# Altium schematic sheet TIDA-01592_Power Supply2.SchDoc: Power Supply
size 431 x 279 mm; Date: Not shown in title block; ApprovedBy: Not shown in title block; CheckedBy: Not shown in title block; Author: Not shown in title block; CompanyName: Not shown in title block; DrawnBy: Abhishek Vishwa; Engineer: Abhishek Vishwa; Organization: Not shown in title block; Address1: Not shown in title block; Address2: Not shown in title block; Address3: Not shown in title block; Address4: Not shown in title block; DocumentNumber: 1; Revision: Use project parameter SCH_Rev; SheetNumber: 3; SheetTotal: 5; PageSetup: Record=PageOptions¦CenterHorizontal=True¦CenterVertical=True¦PrintScale=1.00¦XCorrection=1.00¦YCorrection=1.00¦PrintKind=0¦BorderSize=5000000¦LeftOffset=0¦BottomOffset=0¦Orientation=2¦PaperLength=1000¦PaperWidth=1000¦Scale=100¦PaperSource=15¦PrintQuality=600¦MediaType=1¦DitherType=10¦PaperKind=Letter¦PrintScaleMode=1
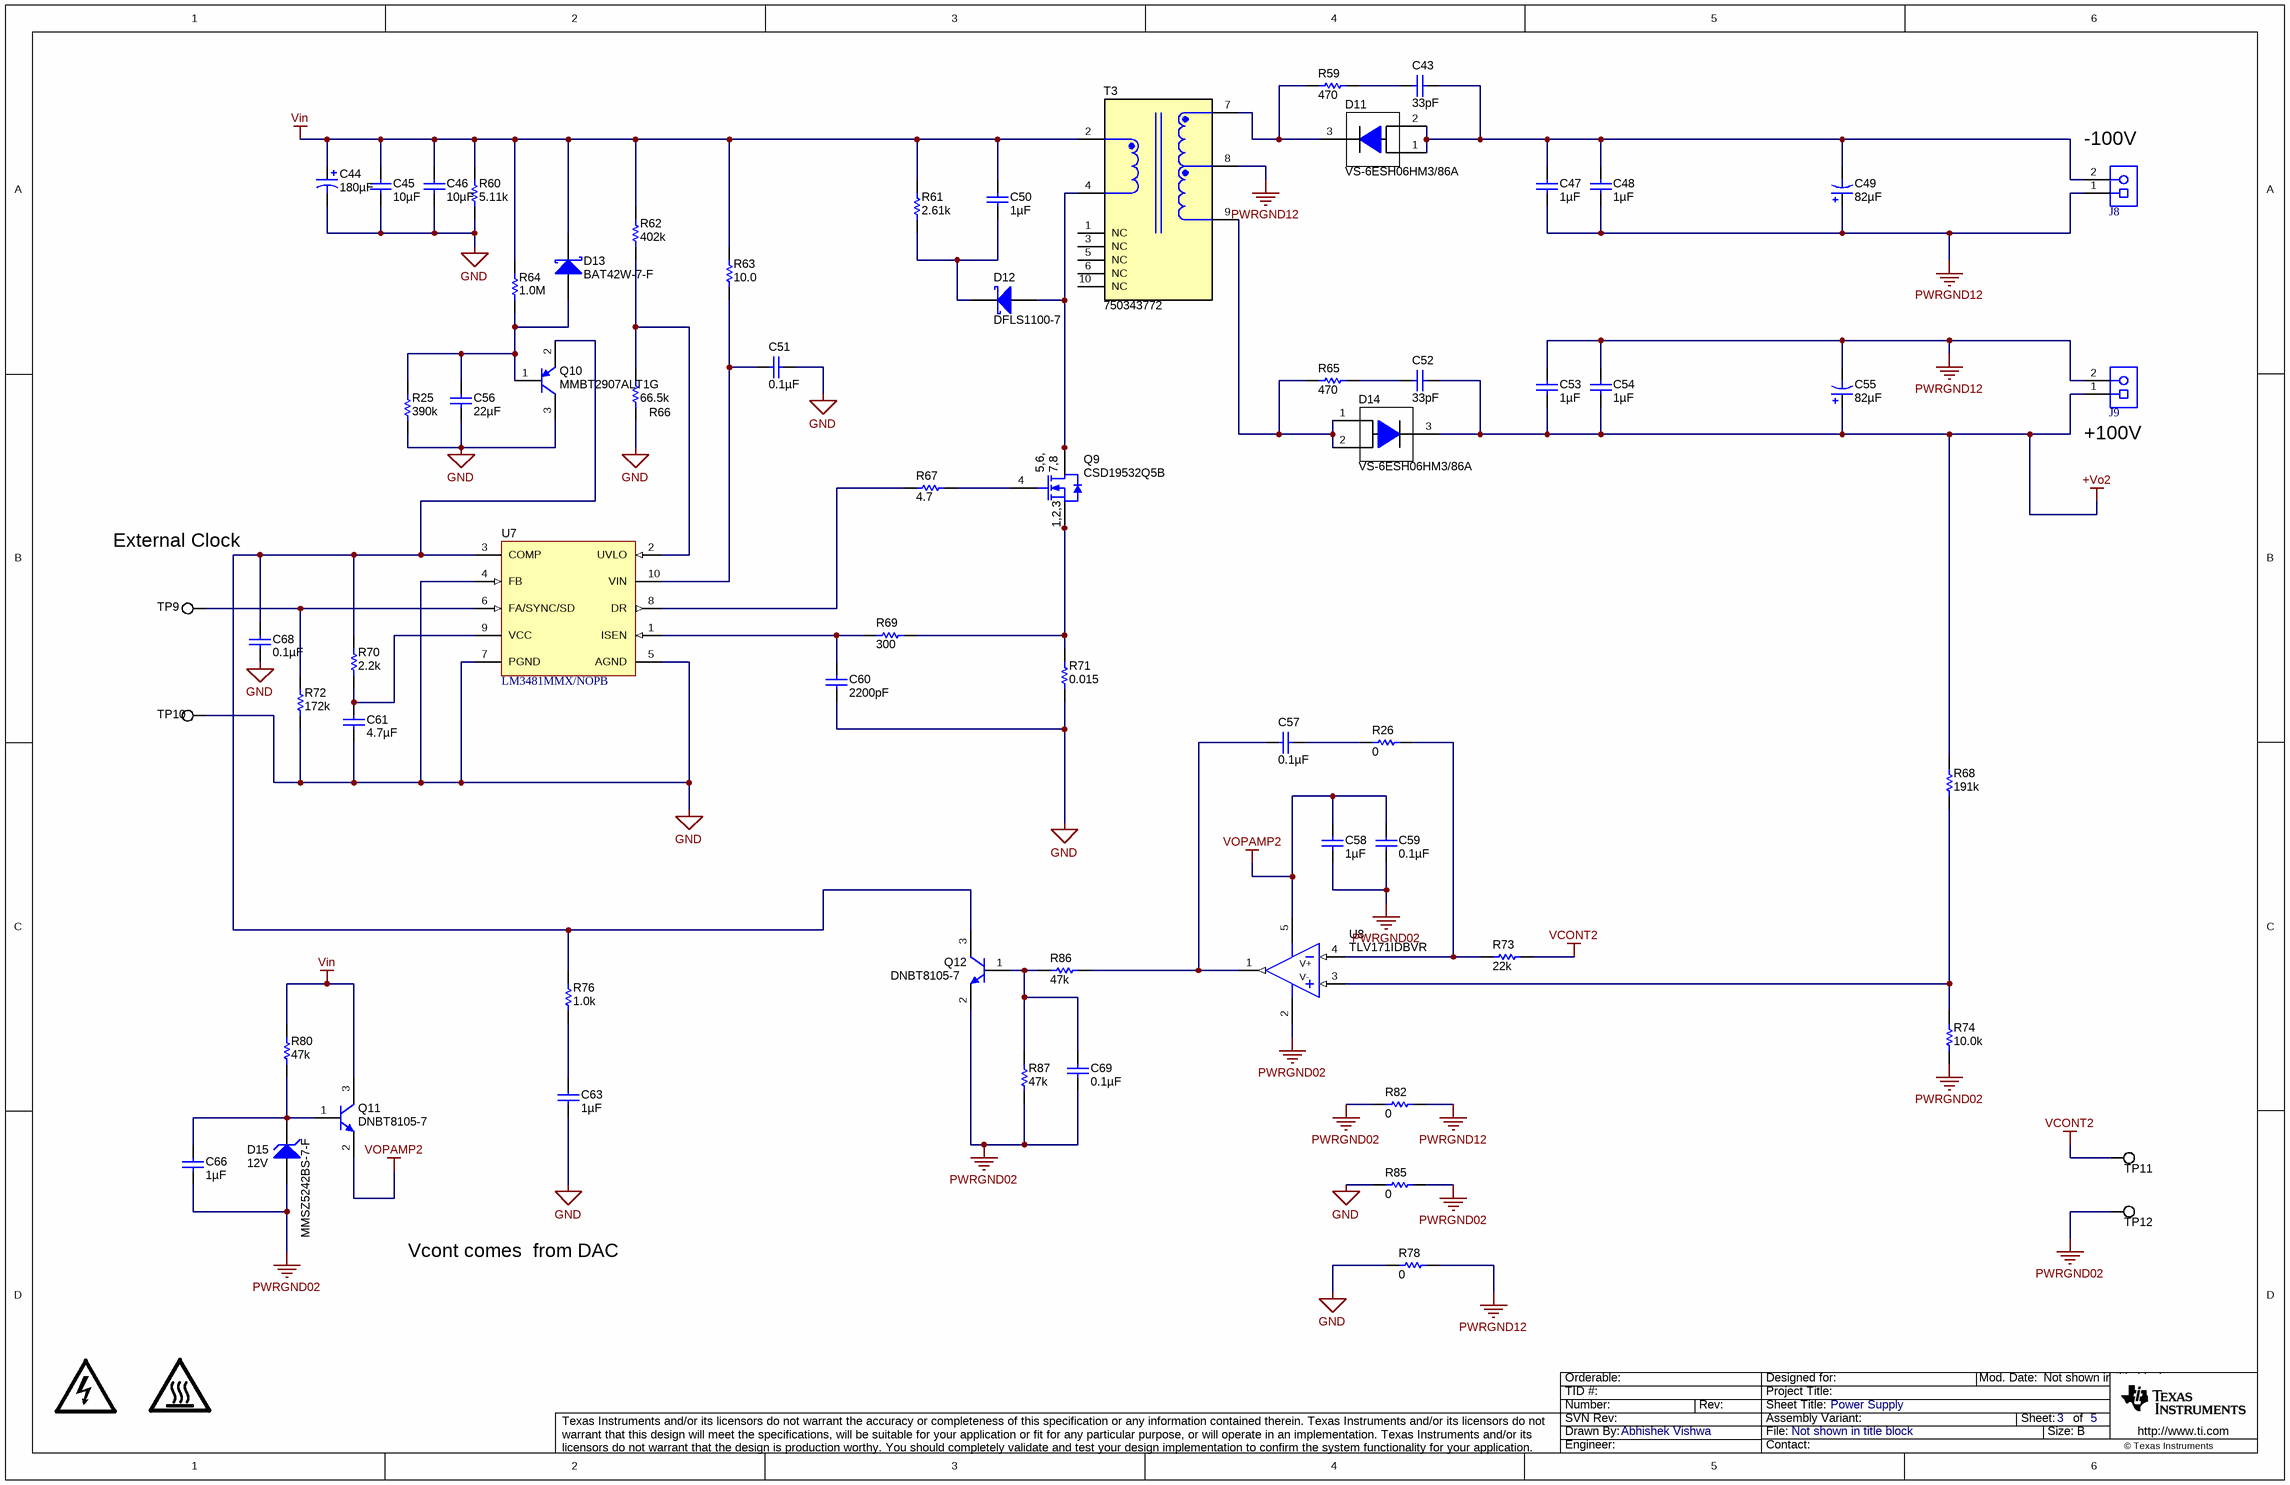
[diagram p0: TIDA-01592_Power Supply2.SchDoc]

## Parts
C43  ValueDisplayed: 33pF  [1206]  (hidden comment: 12067A330JAT2A)
C44  ValueDisplayed: 180µF  [FC_630x1120]  (hidden comment: 35TXW180MEFC6.3X25)
C45  ValueDisplayed: 10µF  [1206_180]  (hidden comment: GRM31CR61H106KA12L)
C46  ValueDisplayed: 10µF  [1206_180]  (hidden comment: GRM31CR61H106KA12L)
C47  ValueDisplayed: 1µF  [1812_180]  (hidden comment: C4532X7T2E105M250KE)
C48  ValueDisplayed: 1µF  [1812_180]  (hidden comment: C4532X7T2E105M250KE)
C49  ValueDisplayed: 82µF  [NHG_1000x2000]  (hidden comment: UCY2C820MPD9)
C50  ValueDisplayed: 1µF  [1206_180]  (hidden comment: GRM31CR72A105KA01L)
C51  ValueDisplayed: 0.1µF  [0603]  (hidden comment: GRM188R71H104KA93D)
C52  ValueDisplayed: 33pF  [1206]  (hidden comment: 12067A330JAT2A)
C53  ValueDisplayed: 1µF  [1812_180]  (hidden comment: C4532X7T2E105M250KE)
C54  ValueDisplayed: 1µF  [1812_180]  (hidden comment: C4532X7T2E105M250KE)
C55  ValueDisplayed: 82µF  [NHG_1000x2000]  (hidden comment: UCY2C820MPD9)
C56  ValueDisplayed: 22µF  [0805_HV1]  (hidden comment: C2012X5R1V226M125AC)
C57  ValueDisplayed: 0.1µF  [0603]  (hidden comment: GRM188R71H104KA93D)
C58  ValueDisplayed: 1µF  [0603]  (hidden comment: UMK107AB7105KA-T)
C59  ValueDisplayed: 0.1µF  [0603]  (hidden comment: GRM188R71H104KA93D)
C60  ValueDisplayed: 2200pF  [0402]  (hidden comment: GRM155R61H222KA01D)
C61  ValueDisplayed: 4.7µF  [0603]  (hidden comment: 0603ZD475KAT2A)
C63  ValueDisplayed: 1µF  [0603]  (hidden comment: C0603C105K3RACTU)
C66  ValueDisplayed: 1µF  [0603]  (hidden comment: C0603C105K3RACTU)
C68  ValueDisplayed: 0.1µF  [0603]  (hidden comment: GRM188R71H104KA93D)
C69  ValueDisplayed: 0.1µF  [0603]  (hidden comment: GRM188R71H104KA93D)
D11  VS-6ESH06HM3/86A  [TO-277A]
D12  DFLS1100-7  [PowerDI123]
D13  BAT42W-7-F  [SOD-123]
D14  VS-6ESH06HM3/86A  [TO-277A]
D15  MMSZ5242BS-7-F  value 12V  [SOD-323]
J8  1727010  [PhoenixConact_1727010]  (value not drawn)
J9  1727010  [PhoenixConact_1727010]  (value not drawn)
LOGO2  CAUTION HOT SURFACE  [IEC_HotSurface_Small]  (value not drawn)  (graphical)
LOGO8  DANGER HIGH VOLTAGE  [IEC_HighVoltage_Small]  (value not drawn)  (graphical)
Q9  CSD19532Q5B  [DNK0008A]
Q10  MMBT2907ALT1G  [SOT-23]
Q11  DNBT8105-7  [SOT-23]
Q12  DNBT8105-7  [SOT-23]
R25  ValueDisplayed: 390k  [0603]  (hidden comment: CRCW0603390KJNEA)
R26  ValueDisplayed: 0  [0402]  (hidden comment: CRCW04020000Z0ED)
R59  ValueDisplayed: 470  [1206]  (hidden comment: CRCW1206470RJNEA)
R60  ValueDisplayed: 5.11k  [TNPW0603]  (hidden comment: TNPW06035K11BEEA)
R61  ValueDisplayed: 2.61k  [2010]  (hidden comment: CRCW20102K61FKEF)
R62  ValueDisplayed: 402k  [0603]  (hidden comment: CRCW0603402KFKEA)
R63  R4: 10.0  [0603]  (hidden comment: CRCW060310R0FKEAHP)
R64  ValueDisplayed: 1.0M  [0603]  (hidden comment: CRCW06031M00JNEA)
R65  ValueDisplayed: 470  [1206]  (hidden comment: CRCW1206470RJNEA)
R66  ValueDisplayed: 66.5k  [0603]  (hidden comment: CRCW060366K5FKEA)
R67  ValueDisplayed: 4.7  [0603]  (hidden comment: CRCW06034R70JNEA)
R68  ValueDisplayed: 191k  [0603]  (hidden comment: CRCW0603191KFKEA)
R69  ValueDisplayed: 300  [0603]  (hidden comment: CRCW0603300RJNEA)
R70  ValueDisplayed: 2.2k  [0603]  (hidden comment: ERJ-3GEYJ222V)
R71  ValueDisplayed: 0.015  [2010]  (hidden comment: WSL2010R0150FEA18)
R72  ValueDisplayed: 172k  [0603]  (hidden comment: RT0603DRE07172KL)
R73  ValueDisplayed: 22k  [0603]  (hidden comment: CRCW060322K0JNEA)
R74  ValueDisplayed: 10.0k  [0603]  (hidden comment: CRCW060310K0FKEA)
R76  ValueDisplayed: 1.0k  [0603]  (hidden comment: CRCW06031K00JNEA)
R78  ValueDisplayed: 0  [2010L]  (hidden comment: CRCW20100000Z0EF)
R80  ValueDisplayed: 47k  [1206]  (hidden comment: CRCW120647K0JNEA)
R82  ValueDisplayed: 0  [2010L]  (hidden comment: CRCW20100000Z0EF)
R85  ValueDisplayed: 0  [2010L]  (hidden comment: CRCW20100000Z0EF)
R86  ValueDisplayed: 47k  [0603]  (hidden comment: RC0603JR-0747KL)
R87  ValueDisplayed: 47k  [0603]  (hidden comment: RC0603JR-0747KL)
T3  750343772  [Wurth_EE16_7_5_5278]
TP9  5002  [Keystone5002]  (value not drawn)
TP10  5002  [Keystone5002]  (value not drawn)
TP11  5002  [Keystone5002]  (value not drawn)
TP12  5002  [Keystone5002]  (value not drawn)
U7  LM3481MMX/NOPB  [MUB10A_N]
U8  TLV171IDBVR  [DBV0005A_N]

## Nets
+Vo2: C52.1 C53.2 C54.2 C55.1(+) D14.3(K) J9.1 R68.2
GND: C44.2(-) C45.2 C46.2 C51.1 C56.2 C60.2 C61.2 C63.2 C68.1 Q10.3(C) R25.1 R60.1 R66.1 R71.1 R72.1 R78.1 R85.1 TP10.1 U7.4(FB) U7.5(AGND) U7.7(PGND)
PWRGND02: C58.2 C59.2 C66.2 C69.1 D15.2(A) Q12.2(E) R74.2 R82.1 R85.2 R87.2 TP12.1 U8.2(V-)
PWRGND12: C47.2 C48.2 C49.1(+) C53.1 C54.1 C55.2(-) J8.1 J9.2 R78.2 R82.2 T3.8
VCONT2: R73.2 TP11.1
Vin: C44.1(+) C45.1 C46.1 C50.1 D13.1(K) Q11.3(C) R60.2 R61.2 R62.2 R63.1 R64.2 R80.2 T3.2
VOPAMP2: C58.1 C59.1 Q11.2(E) U8.5(V+)
NetC43_1: C43.1 C47.1 C48.1 C49.2(-) D11.1(A) D11.2(A) J8.2
NetC43_2: C43.2 R59.2
NetC50_2: C50.2 D12.1(K) R61.1
NetC51_2: C51.2 R63.2 U7.10(VIN)
NetC52_2: C52.2 R65.2
NetC56_1: C56.1 D13.2(A) Q10.1(B) R25.2 R64.1
NetC57_1: C57.1 R86.1 U8.1(OUT)
NetC57_2: C57.2 R26.1
NetC60_1: C60.1 R69.1 U7.1(ISEN)
NetC61_1: C61.1 R70.2 U7.9(VCC)
NetC63_1: C63.1 R76.1
NetC66_1: C66.1 D15.1(K) Q11.1(B) R80.1
NetC68_2: C68.2 Q10.2(E) Q12.3(C) R70.1 R76.2 U7.3(COMP)
NetC69_2: C69.2 Q12.1(B) R86.2 R87.1
NetD11_3: D11.3(K) R59.1 T3.7
NetD12_2: D12.2(A) Q9.5(D) Q9.6(D) Q9.7(D) Q9.8(D) Q9.9(D) T3.4
NetD14_1: D14.1(A) D14.2(A) R65.1 T3.9
NetQ9_1: Q9.1(S) Q9.2(S) Q9.3(S) R69.2 R71.2
NetQ9_4: Q9.4(G) R67.2
NetR26_2: R26.2 R73.1 U8.4(IN-)
NetR62_1: R62.1 R66.2 U7.2(UVLO)
NetR67_1: R67.1 U7.8(DR)
NetR68_1: R68.1 R74.1 U8.3(IN+)
NetR72_2: R72.2 TP9.1 U7.6(FA/SYNC/SD)

Not connected (* = marked no-connect by the designer): T3 1(NC) 3(NC) 5(NC) 6(NC) 10(NC)

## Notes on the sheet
- (near J8) -100V
- (near J9) +100V
- External Clock Synchronization
- Vcont comes  from DAC

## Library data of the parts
C43 C52 = 12067A330JAT2A: CAP, CERM, 33 pF, 500 V,+/- 5%, C0G/NP0, 1206; Manufacturer: AVX; Polarized: N; CompType: Capacitor; Value: 33pF; U/M: EA; Cap_F: 0.000000000033; Tolerance_%: 5; VDC_V: 500; Value2: 500V; TaMin_C: -55; TaMax_C: 125; SizeArea_mm2: 5.12; SizeAreaWB_mm2: 10.92; SizeX_mm: 3.2; SizeY_mm: 1.6; SizeZ_mm: 1.35; AEC Category: Q200; Green_Lifecycle: Not Set; Green_REACh: Incomplete
C44 = EEU-FC1V470: CAP, AL, 180 µF, 35 V, +/- 20%, TH; Manufacturer: Rubycon; Polarized: Y; CompType: Capacitor; Value: 180uF; U/M: EA; Cap_F: 0.000180; Tolerance_%: 20; VDC_V: 35; Value2: 35V; IRMS_A: 0.29; TaMin_C: -55; TaMax_C: 105; Cap_Case: 6.3x11.2mm; SizeAreaWB_mm2: 68.89; SizeArea_mm2: 39.69; SizeX_mm: 6.3; SizeZ_mm: 12.2; AEC Category: Q200; AEC Grade: 2
C45 C46 = GRM31CR61H106KA12L: CAP, CERM, 10 µF, 50 V,+/- 10%, X5R, 1206; Manufacturer: MuRata; Polarized: N; CompType: Capacitor; Value: 10uF; U/M: EA; Cap_F: 0.00001; Tolerance_%: 10; VDC_V: 50; Value2: 50V; TaMin_C: -55; TaMax_C: 85; Cap_Case: 1206; SizeArea_mm2: 5.12; SizeAreaWB_mm2: 10.92; SizeX_mm: 3.2; SizeY_mm: 1.6; SizeZ_mm: 1.8; AEC Category: Q200; Green_Lifecycle: Active; Green_REACh: Passed
C47 C48 C53 C54 = C4532X7R1H105K160KA: CAP, CERM, 1 µF, 250 V,+/- 20%, X7T, 1812; Manufacturer: TDK Corporation; Polarized: N; CompType: Capacitor; Value: 1uF; U/M: EA; Cap_F: 0.000001; Tolerance_%: 20; ESR_ohm: 0.007217; Value1: 0.007217 ohm; VDC_V: 50; Value2: 250V; IRMS_A: 2.85919; TaMin_C: -55; TaMax_C: 125; Cap_Case: 1812; SizeArea_mm2: 14.4; SizeAreaWB_mm2: 23.1; SizeX_mm: 4.5; SizeY_mm: 3.2; SizeZ_mm: 1.8; AEC Category: Q200
C49 C55 = ECA-2AHG101: CAP, AL, 82 µF, 160 V, +/- 20%, TH; Manufacturer: Nichicon; Polarized: Y; CompType: Capacitor; Value: 82uF; U/M: EA; Cap_F: 0.0001; Tolerance_%: 20; VDC_V: 160; Value2: 160V; IRMS_A: 0.265; TaMin_C: -55; TaMax_C: 105; Cap_Case: 10x20mm; SizeAreaWB_mm2: 144; SizeArea_mm2: 100; SizeX_mm: 10; SizeZ_mm: 22; AEC Category: Q200; Green_Lifecycle: Active; Green_REACh: Passed
C50 = GRM31CR72A105KA01L: CAP, CERM, 1 µF, 100 V,+/- 10%, X7R, 1206; Manufacturer: MuRata; Polarized: N; CompType: Capacitor; Value: 1uF; U/M: EA; Cap_F: 0.000001; Tolerance_%: 10; VDC_V: 100; Value2: 100V; TaMin_C: -55; TaMax_C: 125; Cap_Case: 1206; SizeArea_mm2: 5.12; SizeAreaWB_mm2: 10.92; SizeX_mm: 3.2; SizeY_mm: 1.6; SizeZ_mm: 1.8; AEC Category: Q200; Green_Lifecycle: Active; Green_REACh: Passed
C51 C57 C59 C68 C69 = GRM188R71H104KA93D: CAP, CERM, 0.1 µF, 50 V,+/- 10%, X7R, 0603; Manufacturer: MuRata; Polarized: N; CompType: Capacitor; Value: 0.1uF; U/M: EA; Cap_F: 0.0000001; Tolerance_%: 10; VDC_V: 50; Value2: 50V; TaMin_C: -55; TaMax_C: 125; SizeArea_mm2: 1.28; SizeAreaWB_mm2: 4.68; SizeX_mm: 1.6; SizeY_mm: 0.8; SizeZ_mm: 1; AEC Category: Q200; Green_Lifecycle: Active; Green_REACh: Passed
C56 = GRM21BC81C226ME44L: CAP, CERM, 22 µF, 35 V,+/- 20%, X5R, 0805; Manufacturer: TDK Corporation; Polarized: N; CompType: Capacitor; Value: 22uF; U/M: EA; Cap_F: 0.000022; Tolerance_%: 20; VDC_V: 16; Value2: 35V; TempCo: X6S; TaMin_C: -55; TaMax_C: 105; Cap_Case: 0805; SizeArea_mm2: 2.5; SizeAreaWB_mm2: 6.75; SizeX_mm: 2; SizeY_mm: 1.25; SizeZ_mm: 1.45; AEC Category: Q200
C58 = UMK107AB7105KA-T: CAP, CERM, 1 µF, 50 V,+/- 10%, X7R, 0603; Manufacturer: Taiyo Yuden; Polarized: N; CompType: Capacitor; Value: 1uF; U/M: EA; Cap_F: 0.000001; Tolerance_%: 10; VDC_V: 50; Value2: 50V; TaMin_C: -55; TaMax_C: 125; SizeArea_mm2: 1.28; SizeAreaWB_mm2: 4.68; SizeX_mm: 1.6; SizeY_mm: 0.8; SizeZ_mm: 1; AEC Category: Q200; Green_Lifecycle: Active; Green_REACh: Passed
C60 = GRM155R61H222KA01D: CAP, CERM, 2200 pF, 50 V,+/- 10%, X5R, 0402; Manufacturer: MuRata; Polarized: N; CompType: Capacitor; Value: 2200pF; U/M: EA; Cap_F: 0.0000000022; Tolerance_%: 10; VDC_V: 50; Value2: 50V; TaMin_C: -55; TaMax_C: 85; SizeArea_mm2: 0.5; SizeAreaWB_mm2: 3; SizeX_mm: 1; SizeZ_mm: 0.6; AEC Category: Q200; Green_Lifecycle: Active; Green_REACh: Passed
C61 = 0603ZD475KAT2A: CAP, CERM, 4.7 µF, 10 V,+/- 10%, X5R, 0603; Manufacturer: AVX; Polarized: N; CompType: Capacitor; Value: 4.7uF; U/M: EA; Cap_F: 0.0000047; Tolerance_%: 10; Value2: 10V; TaMin_C: -55; TaMax_C: 85; SizeArea_mm2: 1.28; SizeAreaWB_mm2: 4.68; SizeX_mm: 1.6; SizeY_mm: 0.8; SizeZ_mm: 1; AEC Category: Q200; Green_Lifecycle: Active; Green_REACh: Passed
C63 C66 = C0603C105K3RACTU: CAP, CERM, 1 µF, 25 V,+/- 10%, X7R, 0603; Manufacturer: Kemet; Polarized: N; CompType: Capacitor; Value: 1uF; U/M: EA; Cap_F: 0.000001; Tolerance_%: 10; VDC_V: 25; Value2: 25V; TaMin_C: -55; TaMax_C: 125; SizeArea_mm2: 1.28; SizeAreaWB_mm2: 4.68; SizeX_mm: 1.6; SizeY_mm: 0.8; SizeZ_mm: 1; AEC Category: Q200; Green_Lifecycle: Active; Green_REACh: Passed
D11 D14 = VS-6ESH06HM3/86A: Diode, Hyperfast, 600 V, 6 A, AEC-Q101, TO-277A; Manufacturer: Vishay-Semiconductor; SymbolCreator: a0412235; U/M: EA; Vf_V: 1.05; Value: 600V; Value1: 6A; Value2: 1.05V; Io_A: 6; Vr_V: 600; TJmax_C: 175; RJC_CperW: 3.5; SizeAreaWB_mm2: 57.375; SizeArea_mm2: 30.875; SizeX_mm: 6.5; SizeY_mm: 4.75; SizeZ_mm: 1.2; AEC Category: Q101; AEC Qualified: Y
D12 = DFLS1100-7: Diode, Schottky, 100 V, 1 A, PowerDI123; Manufacturer: Diodes Inc.; U/M: EA; Vf_V: 0.77; Value: 100V; Value1: 1A; Value2: 0.77V; Io_A: 1; Vr_V: 100; TJmax_C: 175; RJC_CperW: 7; SizeAreaWB_mm2: 13.066; SizeArea_mm2: 6.586; SizeX_mm: 3.7; SizeY_mm: 1.78; SizeZ_mm: 0.98; AEC Category: Q101; Green_Lifecycle: Active; Green_REACh: Passed
D13 = BAT42W-7-F: Diode, Schottky, 30 V, 0.2 A, SOD-123; Manufacturer: Diodes Inc.; U/M: EA; Vf_V: 1; Value: 30V; Value1: 0.2A; Value2: 1V; Io_A: 0.2; Vr_V: 30; SizeAreaWB_mm2: 13.095; SizeArea_mm2: 6.545; SizeX_mm: 3.85; SizeY_mm: 1.7; SizeZ_mm: 1.35; AEC Category: Q101; Green_Lifecycle: Not Set; Green_REACh: Incomplete
D15 = MMSZ5242BS-7-F: Diode, Zener, 12 V, 200 mW, SOD-323; Manufacturer: Diodes Inc.; SymbolCreator: a0412235; U/M: EA; Power_W: 0.2; Vz_V: 12; Value1: 0.2W; RJA_CperW: 350; SizeAreaWB_mm2: 8.695; SizeArea_mm2: 3.645; SizeX_mm: 2.7; SizeY_mm: 1.35; SizeZ_mm: 1; AEC Category: Q101
J8 J9 = 1727010: Conn Term Block, 2POS, 3.81mm, TH; Manufacturer: Phoenix Contact; SymbolCreator: a0412235; CompType: Terminal Block
LOGO2 = IEC_HotSurface: IEC 61010-1 Hot Surface Warning; SymbolCreator: a0412235
LOGO8 = IEC_HighVoltage: IEC 61010-1 High Voltage Warning; SymbolCreator: a0412235
Q9 = CSD19532Q5B: MOSFET, N-CH, 100 V, 17 A, DNK0008A (VSON-CLIP-8); Manufacturer: Texas Instruments; Alternate Manufacturer: None; U/M: EA; ChType: N; Value: 100V; VdsMax_V: 100; Value1: ? ohm; Value2: 48 nC; QgTyp_nC: 48; Vgs_V: 20; IdsMax_A: 17; SizeAreaWB_mm2: 56; SizeArea_mm2: 30; SizeX_mm: 6; SizeY_mm: 5; SizeZ_mm: 1; AEC Category: Q101
Q10 = MMBT2907ALT1G, ON Semiconductor: Transistor, PNP, 60 V, 0.6 A, SOT-23; CompType: BJT; PNP: 1; NPN: 0; Vceo_V: 60; Vcesat1_V: 1.6; Value: 60 V; IcRated_A: 0.6; Value1: 0.6 A; TaMin_C: -55; TaMax_C: 150; SizeAreaWB_mm2: 14; SizeArea_mm2: 7.5; SizeX_mm: 2.5; SizeY_mm: 3; SizeZ_mm: 1.1; U/M: EA; AEC Category: Q101; Green_Lifecycle: Active; Green_REACh: Passed
Q11 Q12 = DNBT8105-7, Diodes Inc.: Transistor, NPN, 60 V, 1 A, AEC-Q101, SOT-23; CompType: BJT; PNP: 0; NPN: 1; Vceo_V: 60; Vcesat1_V: 0.25; Value: 60 V; Value1: 1 A; HfeMax: 300; TaMin_C: -55; TaMax_C: 150; SizeAreaWB_mm2: 14; SizeArea_mm2: 7.5; SizeX_mm: 2.5; SizeY_mm: 3; SizeZ_mm: 1.1; U/M: EA; AEC Category: Q101; AEC Qualified: Y; Green_Lifecycle: Not Set; Green_REACh: Incomplete
R25 = CRCW0603390KJNEA: RES, 390 k, 5%, 0.1 W, 0603; Manufacturer: Vishay-Dale; CompType: Resistor; Value: 390k; Res_ohm: 390000; Tolerance_%: 5; Power_W: 0.1; Value2: 0.1W; VDC_V: 75; TempCo: 200 ppm/C; SizeArea_mm2: 1.28; SizeX_mm: 1.6; SizeY_mm: 0.8; SizeZ_mm: 1; EIA_Code: E24; U/M: EA; AEC Category: Q200
R26 = CRCW04020000Z0ED: RES, 0, 5%, 0.063 W, 0402; Manufacturer: Vishay-Dale; CompType: Resistor; Value: 0; Value_Code: 0000; Tolerance_%: 5; Power_W: 0.063; Value2: 0.063W; VDC_V: 50; TempCo: 200 ppm/C; SizeArea_mm2: 0.5; SizeX_mm: 1; SizeZ_mm: 0.6; EIA_Code: E24; U/M: EA; AEC Category: Q200; Green_Lifecycle: Active; Green_REACh: Passed
R59 R65 = CRCW1206470RJNEA: RES, 470, 5%, 0.25 W, 1206; Manufacturer: Vishay-Dale; CompType: Resistor; Value: 470; Value_Code: 470R; Tolerance_%: 5; Power_W: 0.25; Value2: 0.25W; VDC_V: 200; TempCo: 200 ppm/C; SizeArea_mm2: 5.12; SizeX_mm: 3.2; SizeY_mm: 1.6; SizeZ_mm: 1.35; EIA_Code: E24; U/M: EA; AEC Category: Q200
R60 = TNPW06035K11BEEA: RES, 5.11 k, 0.1%, 0.1 W, AEC-Q200 Grade 1, 0603; Manufacturer: Vishay-Dale; CompType: Resistor; Value: 5.11k; Res_ohm: 5110; Value_Code: 5k11; Tolerance_%: 0.1; Value2: 0.1W; VDC_V: 75; TempCo: 25 ppm/C; SizeArea_mm2: 1.36; SizeX_mm: 1.6; SizeY_mm: 0.85; SizeZ_mm: 0.55; EIA_Code: E192; U/M: EA; AEC Category: Q200; AEC Qualified: Y; AEC Grade: 1
R61 = CRCW20102K61FKEF: RES, 2.61 k, 1%, 0.75 W, AEC-Q200 Grade 0, 2010; Manufacturer: Vishay-Dale; CompType: Resistor; Value: 2.61k; Res_ohm: 2610; Value_Code: 2k61; Tolerance_%: 1; Power_W: 0.75; Value2: 0.75W; VDC_V: 400; TempCo: 100 ppm/C; SizeArea_mm2: 12.5; SizeX_mm: 5; SizeY_mm: 2.5; SizeZ_mm: 1.66; EIA_Code: E96; U/M: EA; AEC Category: Q200; AEC Qualified: Y; AEC Grade: 0
R62 = CRCW0603402KFKEA: RES, 402 k, 1%, 0.1 W, 0603; Manufacturer: Vishay-Dale; CompType: Resistor; Value: 402k; Res_ohm: 402000; Tolerance_%: 1; Power_W: 0.1; Value2: 0.1W; VDC_V: 75; TempCo: 100 ppm/C; SizeArea_mm2: 1.28; SizeX_mm: 1.6; SizeY_mm: 0.8; EIA_Code: E96; U/M: EA; AEC Category: Q200; Green_Lifecycle: Active; Green_REACh: Passed
R63 = CRCW060310R0FKEAHP: RES, 10.0, 1%, 0.25 W, 0603; Manufacturer: Vishay-Dale; CompType: Resistor; Value: 10.0; Res_ohm: 10; Value_Code: 10R0; Tolerance_%: 1; Power_W: 0.25; Value2: 0.25W; VDC_V: 75; TempCo: 100 ppm/C; SizeArea_mm2: 1.28; SizeX_mm: 1.6; SizeY_mm: 0.8; EIA_Code: E96; U/M: EA; AEC Category: Q200; Green_Lifecycle: Active; Green_REACh: Passed
R64 = CRCW06031M00JNEA: RES, 1.0 M, 5%, 0.1 W, 0603; Manufacturer: Vishay-Dale; CompType: Resistor; Value: 1.0Meg; Res_ohm: 1000000; Value_Code: 1M00; Tolerance_%: 5; Power_W: 0.1; Value2: 0.1W; VDC_V: 75; TempCo: 200 ppm/C; SizeArea_mm2: 1.28; SizeX_mm: 1.6; SizeY_mm: 0.8; SizeZ_mm: 1; EIA_Code: E24; U/M: EA; AEC Category: Q200; Green_Lifecycle: Active; Green_REACh: Passed
R66 = CRCW060366K5FKEA: RES, 66.5 k, 1%, 0.1 W, 0603; Manufacturer: Vishay-Dale; CompType: Resistor; Value: 66.5k; Res_ohm: 66500; Value_Code: 66k5; Tolerance_%: 1; Power_W: 0.1; Value2: 0.1W; VDC_V: 75; TempCo: 100 ppm/C; SizeArea_mm2: 1.28; SizeX_mm: 1.6; SizeY_mm: 0.8; EIA_Code: E96; U/M: EA; AEC Category: Q200; Green_Lifecycle: Active; Green_REACh: Passed
R67 = CRCW06034R70JNEA: RES, 4.7, 5%, 0.1 W, 0603; Manufacturer: Vishay-Dale; CompType: Resistor; Value: 4.7; Value_Code: 4R70; Tolerance_%: 5; Power_W: 0.1; Value2: 0.1W; VDC_V: 75; TempCo: 200 ppm/C; SizeArea_mm2: 1.28; SizeX_mm: 1.6; SizeY_mm: 0.8; SizeZ_mm: 1; EIA_Code: E24; U/M: EA; AEC Category: Q200; Green_Lifecycle: Active; Green_REACh: Passed
R68 = CRCW0603191KFKEA: RES, 191 k, 1%, 0.1 W, 0603; Manufacturer: Vishay-Dale; CompType: Resistor; Value: 191k; Res_ohm: 191000; Tolerance_%: 1; Power_W: 0.1; Value2: 0.1W; VDC_V: 75; TempCo: 100 ppm/C; SizeArea_mm2: 1.28; SizeX_mm: 1.6; SizeY_mm: 0.8; EIA_Code: E96; U/M: EA; AEC Category: Q200; Green_Lifecycle: Active; Green_REACh: Passed
R69 = CRCW0603300RJNEA: RES, 300, 5%, 0.1 W, 0603; Manufacturer: Vishay-Dale; CompType: Resistor; Value: 300; Value_Code: 300R; Tolerance_%: 5; Power_W: 0.1; Value2: 0.1W; VDC_V: 75; TempCo: 200 ppm/C; SizeArea_mm2: 1.28; SizeX_mm: 1.6; SizeY_mm: 0.8; SizeZ_mm: 1; EIA_Code: E24; U/M: EA; AEC Category: Q200; Green_Lifecycle: Active; Green_REACh: Passed
R70 = ERJ-3GEYJ222V: RES, 2.2 k, 5%, 0.1 W, AEC-Q200 Grade 0, 0603; Manufacturer: Panasonic; CompType: Resistor; Value: 2.2k; Res_ohm: 2200; Value_Code: 2k20; Tolerance_%: 5; Power_W: 0.1; Value2: 0.1W; VDC_V: 75; TempCo: 200 ppm/C; SizeArea_mm2: 1.28; SizeX_mm: 1.6; SizeY_mm: 0.8; SizeZ_mm: 1; EIA_Code: E24; U/M: EA; AEC Category: Q200; AEC Qualified: Y; AEC Grade: 0; Green_Lifecycle: Active; Green_REACh: Passed
R71 = WSL2010R0150FEA18: RES, 0.015, 1%, 1 W, 2010; Manufacturer: Vishay-Dale; CompType: Resistor; Value: 0.015; Value_Code: R015; Tolerance_%: 1; Value2: 1W; TempCo: 75 ppm/C; SizeArea_mm2: 12.5; SizeX_mm: 5; SizeY_mm: 2.5; SizeZ_mm: 1.66; EIA_Code: E96; U/M: EA; AEC Category: Q200
R72 = RT0603DRE07172KL: RES, 172 k, 0.5%, 0.1 W, 0603; Manufacturer: Yageo America; CompType: Resistor; Value: 172k; Res_ohm: 172000; Tolerance_%: 0.5; Power_W: 0.1; Value2: 0.1W; VDC_V: 75; TempCo: 50 ppm/C; SizeArea_mm2: 1.28; SizeX_mm: 1.6; SizeY_mm: 0.8; SizeZ_mm: 1; EIA_Code: E192; U/M: EA; AEC Category: Q200
R73 = CRCW060322K0JNEA: RES, 22 k, 5%, 0.1 W, 0603; Manufacturer: Vishay-Dale; CompType: Resistor; Value: 22k; Res_ohm: 22000; Value_Code: 22k0; Tolerance_%: 5; Power_W: 0.1; Value2: 0.1W; VDC_V: 75; TempCo: 200 ppm/C; SizeArea_mm2: 1.28; SizeX_mm: 1.6; SizeY_mm: 0.8; SizeZ_mm: 1; EIA_Code: E24; U/M: EA; AEC Category: Q200; Green_Lifecycle: Active; Green_REACh: Passed
R74 = CRCW060310K0FKEA: RES, 10.0 k, 1%, 0.1 W, 0603; Manufacturer: Vishay-Dale; CompType: Resistor; Value: 10.0k; Res_ohm: 10000; Value_Code: 10k0; Tolerance_%: 1; Power_W: 0.1; Value2: 0.1W; VDC_V: 75; TempCo: 100 ppm/C; SizeArea_mm2: 1.28; SizeX_mm: 1.6; SizeY_mm: 0.8; EIA_Code: E96; U/M: EA; AEC Category: Q200; Green_Lifecycle: Active; Green_REACh: Passed
R76 = CRCW06031K00JNEA: RES, 1.0 k, 5%, 0.1 W, 0603; Manufacturer: Vishay-Dale; CompType: Resistor; Value: 1.0k; Res_ohm: 1000; Value_Code: 1k00; Tolerance_%: 5; Power_W: 0.1; Value2: 0.1W; VDC_V: 75; TempCo: 200 ppm/C; SizeArea_mm2: 1.28; SizeX_mm: 1.6; SizeY_mm: 0.8; SizeZ_mm: 1; EIA_Code: E24; U/M: EA; AEC Category: Q200; Green_Lifecycle: Active; Green_REACh: Passed
R78 R82 R85 = CRCW20100000Z0EF: RES, 0, 5%, 0.75 W, AEC-Q200 Grade 0, 2010; Manufacturer: Vishay-Dale; CompType: Resistor; Value: 0; Value_Code: 0000; Tolerance_%: 5; Power_W: 0.75; Value2: 0.75W; TempCo: ppm/C; SizeArea_mm2: 12.5; SizeY_mm: 2.5; SizeZ_mm: 1.66; EIA_Code: E24; U/M: EA; AEC Category: Q200; AEC Qualified: Y
R80 = CRCW120647K0JNEA: RES, 47 k, 5%, 0.25 W, 1206; Manufacturer: Vishay-Dale; CompType: Resistor; Value: 47k; Res_ohm: 47000; Value_Code: 47k0; Tolerance_%: 5; Power_W: 0.25; Value2: 0.25W; VDC_V: 200; TempCo: 200 ppm/C; SizeArea_mm2: 5.12; SizeX_mm: 3.2; SizeY_mm: 1.6; SizeZ_mm: 1.35; EIA_Code: E24; U/M: EA; AEC Category: Q200
R86 R87 = RC0603JR-0747KL: RES, 47 k, 5%, 0.1 W, 0603; Manufacturer: Yageo America; CompType: Resistor; Value: 47k; Res_ohm: 47000; Value_Code: 47k0; Tolerance_%: 5; Power_W: 0.1; Value2: 0.1W; VDC_V: 50; TempCo: 100 ppm/C; SizeArea_mm2: 1.28; SizeX_mm: 1.6; SizeY_mm: 0.8; SizeZ_mm: 1; EIA_Code: E24; U/M: EA; AEC Category: Q200; Green_Lifecycle: Active; Green_REACh: Passed
T3 = CMP-0081056-1: Transformer, 13 uH, TH; Manufacturer: Wurth Elektronik; LeakageInd_H: 300nH; Rsec2_ohm: 1.45; SizeAreaWB_mm2: 379.25; DCR_ohm: 0.022; Value: 13uH; Lp: 13; SizeZ_mm: 18.8; SizeX_mm: 16.5; SizeY_mm: 18.5; Ns1toNp: 5.5; SizeArea_mm2: 305.25; Ind_H: 13µH; AEC Qualified: N; Rsec1_ohm: 1; AEC Category: Q200
TP9-TP12 = 5002: Test Point, Miniature, White, TH; Manufacturer: Keystone; CompType: Test Point Loop; ContactFinish: Silver
U7 = LM3481MMX/NOPB: High Efficiency Low-Side N-Channel Controller for Switching Regulators, 10-pin MSOP, Pb-Free; Manufacturer: Texas Instruments; PackageTopMarking: ZXTT*SJPB; PowerWise: N; CompType: MiscPower
U8 = TLV171IDBVR: 36V, Low-Power, RRO, General-Purpose Operational Amplifier, DBV0005A (SOT-23-5); Alternate PartNumber: TLV171IDBVT; Manufacturer: Texas Instruments; SizeArea_mm2: 8.12; SizeAreaWB_mm2: 14.82; SizeX_mm: 2.8; SizeY_mm: 2.9; SizeZ_mm: 1.45; CompType: IC; U/M: EA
